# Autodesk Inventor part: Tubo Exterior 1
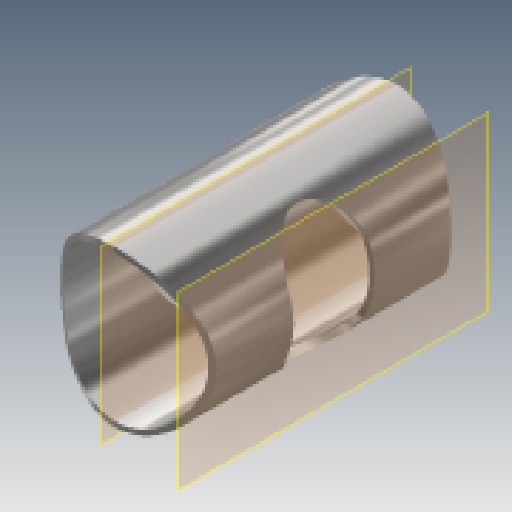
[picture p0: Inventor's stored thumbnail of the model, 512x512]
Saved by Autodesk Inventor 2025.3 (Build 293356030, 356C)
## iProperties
Created: 2025-10
Part Number: Tubo Exterior 1
Material: Hierro, fundido
Document SubType Name: Modeling
Designer: Asus
Density: 7.15 g/cm^3
Appearance: Inoxidable - Bruñido
Author: Asus
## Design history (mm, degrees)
sketch "Boceto1"
  geometry: C1 r 44.45 at (0, 0); C2 r 41.4 at (0, 0); 1 further point
  constraints: 2 centre point, 2 coincident
  dimensions: "d0" = 88.9 diameter of C1; "d1" = 3.05 radial gap between concentric circles of C1 C2
extrude "Extrusión1" new body sketch "Boceto1" stored distance "d2" = 168; taper "d3" = 0 deg
sketch "Boceto4"
  geometry: L1 (44.45, -84)-(44.45, 84) reference; L2 (-44.45, -84)-(44.45, -84) reference; L3 (-44.45, -84)-(-44.45, 84) reference; L4 (-41.4, 84)-(41.4, 84) reference; L5 (44.45, 84)-(-44.45, 84) reference; L6 (44.45, 84)-(44.45, 56.153); L7 (44.45, 84)-(-44.45, 84); L8 (-44.45, 84)-(-44.45, 58.308); L9 (44.45, -84)-(44.45, -61.254); L10 (44.45, -84)-(-44.45, -84); L11 (-44.45, -84)-(-44.45, -62.439); C1 r 80.237 at (0, 0); 5 further points
  constraints: 12 end point, 4 point on line, 2 collinear, 1 centre point, 1 coincident
  dimensions: "d7" = 160.475 diameter of C1
extrude "Extrusión3" cut sketch "Boceto4" extent not by distance; stored distance "d8" = 0; taper "d9" = 0 deg
node "Plano de trabajo1"
sketch "Boceto5"
  geometry: L1 (-15, -23)-(15, -23); L2 (15, -23)-(15, 23); L3 (15, 23)-(-15, 23); L4 (-15, 23)-(-15, -23); L5 (-15, -23)-(15, 23); L6 (15, -23)-(-15, 23); 5 further points
  constraints: 12 end point, 4 midpoint, 2 parallel, 1 horizontal, 1 perpendicular, 6 other
  dimensions: "d10" = 46 distance of L1.end L2.end; "d11" = 30 distance between parallel lines of L4 L2
extrude "Extrusión4" cut sketch "Boceto5" extent not by distance; stored distance "d12" = 0; taper "d13" = 0 deg
node "Sólido1"
